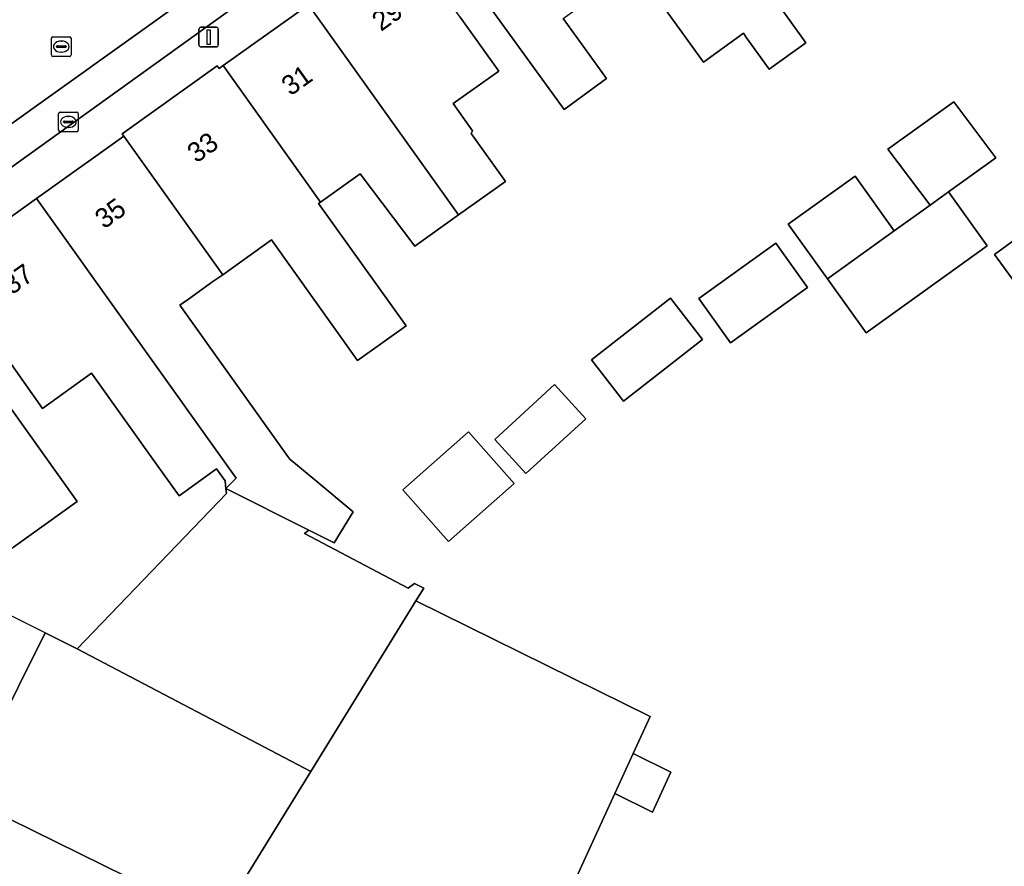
# Model space of a CAD drawing. Extents: x 161881 to 162523, y 381678 to 382381.
# Drawn here: x 162225.8 to 162276, y 381854 to 381897.2 of the extents above; entities that cross this region are included whole.
import ezdxf

# ---------------------------------------------------------------- set-up
doc = ezdxf.new("R2010")
doc.units = 0
for name, color, linetype in [('IMGEO_Erf', 7, 'Continuous'), ('IMGEO_Kolk', 7, 'Continuous'), ('IMGEO_Lichtmast', 7, 'Continuous'), ('IMGEO_Muur', 7, 'Continuous'), ('IMGEO_Pand', 7, 'Continuous'), ('IMGEO_Pand_nummerreeks', 7, 'Continuous'), ('IMGEO_Parkeervlak_open', 7, 'Continuous'), ('IMGEO_Rijbaan_lokaal_open', 7, 'Continuous'), ('IMGEO_Rioolput', 7, 'Continuous'), ('IMGEO_Voetpad_open', 7, 'Continuous')]:
    doc.layers.add(name, color=color, linetype=linetype)

msp = doc.modelspace()

# ---------------------------------------------------------------- linework, layer by layer
at = {"layer": 'IMGEO_Erf'}
for points in [[(162275.507, 381885.197), (162313.123, 381912.663)], [(162308.695, 381857.661), (162317.651, 381867.68), (162320.093, 381870.515), (162317.508, 381873.557), (162311.416, 381880.988), (162315.774, 381884.648), (162315.994, 381884.379), (162316.488, 381884.836), (162316.601, 381884.938), (162316.382, 381885.179), (162318.764, 381887.154), (162318.965, 381886.995), (162319.543, 381887.466), (162319.343, 381887.695), (162320.508, 381888.575), (162315.645, 381894.334), (162318.477, 381896.725), (162315.068, 381901.394), (162281.55, 381876.921), (162275.507, 381885.197)], [(162264.379, 381898.084), (162265.634, 381896.34), (162265.889, 381895.985), (162264.029, 381894.644), (162262.875, 381896.245), (162262.711, 381896.473), (162260.672, 381895.006), (162257.18, 381899.854)], [(162253.538, 381897.228), (162255.74, 381894.172), (162253.587, 381892.585), (162249.531, 381898.176)], [(162248.275, 381897.298), (162250.244, 381894.539), (162247.927, 381892.886), (162248.913, 381891.505), (162248.847, 381891.36), (162250.584, 381888.924), (162248.192, 381887.217), (162245.971, 381885.632), (162243.185, 381889.307), (162241.169, 381887.869), (162241.073, 381887.8), (162245.526, 381881.56), (162243.055, 381879.797), (162238.667, 381885.947), (162236.184, 381884.174), (162235.689, 381883.821), (162234.438, 381882.929), (162234.169, 381882.738), (162233.998, 381882.616), (162239.502, 381874.904), (162239.606, 381874.779), (162240.874, 381873.726), (162242.835, 381872.099), (162241.869, 381870.506), (162240.58, 381871.155), (162240.359, 381870.997), (162245.637, 381868.209), (162245.964, 381868.442), (162246.426, 381868.21), (162246.025, 381867.559), (162257.963, 381861.674), (162257.873, 381861.479), (162257.093, 381859.777), (162259.021, 381858.827), (162258.089, 381856.793), (162256.161, 381857.743), (162252.342, 381849.408)], [(162220.983, 381883.545), (162228.778, 381872.621), (162225.523, 381870.299)], [(162224.418, 381860.495), (162227.131, 381865.927), (162228.776, 381865.106), (162236.37, 381873.024), (162236.344, 381873.289), (162236.307, 381873.673), (162235.876, 381874.277), (162233.959, 381872.909), (162232.792, 381874.544), (162229.505, 381879.151), (162227.003, 381877.365), (162224.754, 381880.517)]]:
    msp.add_lwpolyline(points, dxfattribs=at)
for points in [[(162268.967, 381881.211), (162266.993, 381883.962), (162264.999, 381886.74), (162268.406, 381889.186), (162270.4, 381886.408), (162272.22, 381887.715), (162270.067, 381890.562), (162273.428, 381892.975), (162275.581, 381890.128), (162273.16, 381888.39), (162275.134, 381885.639)], [(162262.055, 381880.707), (162260.435, 381882.963), (162264.362, 381885.782), (162265.981, 381883.526)], [(162258.99, 381882.972), (162260.627, 381880.876), (162256.61, 381877.739), (162254.973, 381879.836)], [(162250.041, 381875.78), (162253.095, 381878.579), (162254.69, 381876.839), (162251.636, 381874.04)], [(162247.681, 381870.576), (162245.353, 381873.207), (162248.707, 381876.176), (162251.035, 381873.545)]]:
    msp.add_lwpolyline(points, close=True, dxfattribs=at)
at = {"layer": 'IMGEO_Kolk'}
for p, q in [((162227.897, 381892.457), (162228.749, 381892.457)), ((162227.822, 381891.531), (162227.822, 381892.383)), ((162228.081, 381891.951), (162228.081, 381891.963)), ((162228.124, 381892), (162228.522, 381892)), ((162228.31, 381892.237), (162228.335, 381892.237)), ((162228.565, 381891.963), (162228.565, 381891.951)), ((162228.823, 381892.383), (162228.823, 381891.531)), ((162228.749, 381891.457), (162227.897, 381891.457)), ((162228.519, 381891.914), (162228.121, 381891.914)), ((162228.333, 381891.677), (162228.308, 381891.677))]:
    msp.add_line(p, q, dxfattribs=at)
for points in [[(162227.897, 381892.457), (162228.749, 381892.457)], [(162227.822, 381891.531), (162227.822, 381892.383)], [(162228.823, 381892.383), (162228.823, 381891.531)], [(162228.749, 381891.457), (162227.897, 381891.457)]]:
    msp.add_lwpolyline(points, dxfattribs=at)
for centre, radius, start, end in [((162227.899, 381892.381), 0.0765, 91.552, 178.448), ((162227.899, 381892.381), 0.0765, 91.552, 178.448), ((162228.747, 381892.381), 0.0765, 1.552, 88.448), ((162228.747, 381892.381), 0.0765, 1.552, 88.448), ((162228.121, 381891.96), 0.0403, 85.8775, 175.7526), ((162228.118, 381891.95), 0.0366, 178.938, 274.7102), ((162228.522, 381891.957), 0.043, 264.8664, 352.4533), ((162228.526, 381891.962), 0.0386, 1.7309, 96.639), ((162227.899, 381891.533), 0.0765, 181.552, 268.448), ((162227.899, 381891.533), 0.0765, 181.552, 268.448), ((162228.747, 381891.533), 0.0765, 271.552, 358.448), ((162228.747, 381891.533), 0.0765, 271.552, 358.448)]:
    msp.add_arc(centre, radius, start, end, dxfattribs=at)
for centre, major_axis, ratio, start_param, end_param in [((162228.309, 381891.957), (-0.387, 0.002), 0.722429, 4.712389, 7.853982), ((162228.334, 381891.957), (-0.39, 0.002), 0.717154, 1.570796, 4.712389)]:
    msp.add_ellipse(centre, major_axis=major_axis, ratio=ratio, start_param=start_param, end_param=end_param, dxfattribs=at)
at = {"layer": 'IMGEO_Lichtmast'}
for p, q in [((162234.971, 381895.879), (162234.971, 381896.679)), ((162234.971, 381896.679), (162234.971, 381895.879)), ((162235.071, 381896.779), (162235.861, 381896.779)), ((162235.861, 381896.779), (162235.071, 381896.779)), ((162235.961, 381896.679), (162235.961, 381895.879)), ((162235.961, 381895.879), (162235.961, 381896.679)), ((162235.861, 381895.779), (162235.071, 381895.779)), ((162235.071, 381895.779), (162235.861, 381895.779))]:
    msp.add_line(p, q, dxfattribs=at)
msp.add_lwpolyline([(162235.391, 381896.654), (162235.541, 381896.654), (162235.541, 381895.904), (162235.391, 381895.904), (162235.391, 381896.654)], dxfattribs=at)
for centre, start, end in [((162235.071, 381896.679), 90, 180), ((162235.071, 381896.679), 90, 180), ((162235.861, 381896.679), 0, 90), ((162235.861, 381896.679), 360, 90), ((162235.071, 381895.879), 180, 270), ((162235.071, 381895.879), 180, 270), ((162235.861, 381895.879), 270, 0), ((162235.861, 381895.879), 270, 0)]:
    msp.add_arc(centre, 0.1, start, end, dxfattribs=at)
at = {"layer": 'IMGEO_Muur'}
msp.add_lwpolyline([(162227.131, 381865.927), (162221.091, 381868.944)], dxfattribs=at)
at = {"layer": 'IMGEO_Pand'}
for points in [[(162315.068, 381901.394), (162318.477, 381896.725), (162315.645, 381894.334), (162320.508, 381888.575), (162331.126, 381897.517), (162324.457, 381905.392), (162322.762, 381907.393), (162318.985, 381904.635), (162313.123, 381912.663), (162275.507, 381885.197), (162281.55, 381876.921)], [(162256.346, 381909.25), (162252.439, 381906.434), (162255.362, 381902.378), (162257.18, 381899.854), (162260.672, 381895.006), (162262.711, 381896.473), (162262.875, 381896.245), (162264.029, 381894.644), (162265.889, 381895.985), (162265.634, 381896.34), (162264.379, 381898.084), (162263.328, 381899.545)], [(162251.586, 381905.819), (162246.608, 381902.233), (162249.531, 381898.176), (162253.587, 381892.585), (162255.74, 381894.172), (162253.538, 381897.228), (162256.328, 381899.238), (162254.509, 381901.762)], [(162248.275, 381897.298), (162245.371, 381901.367), (162240.549, 381897.926), (162248.192, 381887.217), (162250.584, 381888.924), (162248.847, 381891.36), (162248.913, 381891.505), (162247.927, 381892.886), (162250.244, 381894.539)], [(162248.192, 381887.217), (162240.549, 381897.926), (162236.204, 381894.826), (162241.169, 381887.869), (162243.185, 381889.307), (162245.971, 381885.632)], [(162241.073, 381887.8), (162241.169, 381887.869), (162236.204, 381894.826), (162235.998, 381894.679), (162235.903, 381894.812), (162231.059, 381891.355), (162231.152, 381891.225), (162236.184, 381884.174), (162238.667, 381885.947), (162243.055, 381879.797), (162245.526, 381881.56)], [(162272.22, 381887.715), (162273.16, 381888.39), (162275.581, 381890.128), (162273.428, 381892.975), (162270.067, 381890.562)], [(162231.152, 381891.225), (162226.702, 381888.049), (162236.869, 381873.804), (162236.344, 381873.289), (162240.58, 381871.155), (162241.869, 381870.506), (162242.835, 381872.099), (162240.874, 381873.726), (162239.606, 381874.779), (162239.502, 381874.904), (162233.998, 381882.616), (162234.169, 381882.738), (162234.438, 381882.929), (162235.689, 381883.821), (162236.184, 381884.174)], [(162264.999, 381886.74), (162266.993, 381883.962), (162270.4, 381886.408), (162268.406, 381889.186)], [(162226.702, 381888.049), (162221.85, 381884.587), (162224.754, 381880.517), (162227.003, 381877.365), (162229.505, 381879.151), (162232.792, 381874.544), (162233.959, 381872.909), (162235.876, 381874.277), (162236.307, 381873.673), (162236.344, 381873.289), (162236.869, 381873.804)], [(162275.134, 381885.639), (162273.16, 381888.39), (162272.22, 381887.715), (162270.4, 381886.408), (162266.993, 381883.962), (162268.967, 381881.211)], [(162260.435, 381882.963), (162262.055, 381880.707), (162265.981, 381883.526), (162264.362, 381885.782)], [(162220.983, 381883.545), (162219.932, 381882.795), (162219.757, 381883.039), (162214.81, 381879.508), (162214.928, 381879.343), (162215.074, 381879.138), (162214.585, 381878.789), (162215.841, 381877.029), (162216.329, 381877.377), (162219.836, 381872.464), (162220.024, 381872.598), (162224.95, 381870.164), (162225.045, 381870.118), (162225.177, 381870.052), (162225.523, 381870.299), (162228.778, 381872.621)], [(162258.99, 381882.972), (162254.973, 381879.836), (162256.61, 381877.739), (162260.627, 381880.876)], [(162250.041, 381875.78), (162251.636, 381874.04), (162254.69, 381876.839), (162253.095, 381878.579)], [(162248.707, 381876.176), (162245.353, 381873.207), (162247.681, 381870.576), (162251.035, 381873.545)], [(162240.359, 381870.997), (162240.58, 381871.155), (162236.344, 381873.289), (162236.37, 381873.024), (162228.776, 381865.106), (162240.666, 381858.867), (162246.025, 381867.559), (162246.426, 381868.21), (162245.964, 381868.442), (162245.637, 381868.209)], [(162222.972, 381857.598), (162220.321, 381858.911), (162211.275, 381863.392), (162201.278, 381868.442), (162200.189, 381868.993), (162191.173, 381862.471), (162202.159, 381857.074), (162201.802, 381856.284), (162194.508, 381840.175), (162203.692, 381835.979), (162211.21, 381852.547), (162219.706, 381848.467), (162222.963, 381846.903), (162225.821, 381845.53), (162230.931, 381843.076), (162232.406, 381845.468), (162235.949, 381851.214)], [(162252.342, 381849.408), (162256.161, 381857.743), (162257.093, 381859.777), (162257.873, 381861.479), (162257.963, 381861.674), (162246.025, 381867.559), (162240.666, 381858.867), (162235.949, 381851.214), (162232.406, 381845.468), (162238.196, 381842.822), (162238.73, 381843.992), (162242.567, 381842.238), (162241.739, 381840.426), (162234.507, 381824.125), (162235.421, 381823.701), (162236.604, 381820.938), (162238.114, 381820.275), (162238.061, 381820.148), (162238.59, 381819.884), (162238.733, 381819.87), (162242.059, 381827.149), (162244.506, 381832.34), (162249.124, 381842.446)], [(162228.776, 381865.106), (162227.131, 381865.927), (162224.418, 381860.495), (162222.972, 381857.598), (162235.949, 381851.214), (162240.666, 381858.867)], [(162257.093, 381859.777), (162256.161, 381857.743), (162258.089, 381856.793), (162259.021, 381858.827)]]:
    msp.add_lwpolyline(points, close=True, dxfattribs=at)
at = {"layer": 'IMGEO_Parkeervlak_open'}
msp.add_lwpolyline([(162273.463, 381926.395), (162269.991, 381923.887), (162260.256, 381916.887), (162257.825, 381915.139), (162253.349, 381911.92), (162238.365, 381901.138), (162234.555, 381898.412), (162224.359, 381891.116), (162225.354, 381889.595), (162274.088, 381924.659), (162273.358, 381925.677)], dxfattribs=at)
at = {"layer": 'IMGEO_Rijbaan_lokaal_open'}
msp.add_lwpolyline([(162221.475, 381894.082), (162223.84, 381890.752), (162224.359, 381891.116), (162234.555, 381898.412)], dxfattribs=at)
at = {"layer": 'IMGEO_Rioolput'}
for p, q in [((162227.459, 381895.366), (162227.459, 381896.218)), ((162227.534, 381896.292), (162228.386, 381896.292)), ((162227.947, 381896.072), (162227.972, 381896.072)), ((162228.46, 381896.218), (162228.46, 381895.366)), ((162227.718, 381895.786), (162227.718, 381895.798)), ((162228.156, 381895.749), (162227.758, 381895.749)), ((162227.761, 381895.835), (162228.159, 381895.835)), ((162227.97, 381895.512), (162227.945, 381895.512)), ((162228.202, 381895.798), (162228.202, 381895.786)), ((162228.386, 381895.292), (162227.534, 381895.292))]:
    msp.add_line(p, q, dxfattribs=at)
for points in [[(162227.459, 381895.366), (162227.459, 381896.218)], [(162227.534, 381896.292), (162228.386, 381896.292)], [(162228.46, 381896.218), (162228.46, 381895.366)], [(162228.386, 381895.292), (162227.534, 381895.292)]]:
    msp.add_lwpolyline(points, dxfattribs=at)
for centre, radius, start, end in [((162227.536, 381896.216), 0.0765, 91.552, 178.448), ((162227.536, 381896.216), 0.0765, 91.552, 178.448), ((162228.384, 381896.216), 0.0765, 1.552, 88.448), ((162228.384, 381896.216), 0.0765, 1.552, 88.448), ((162227.758, 381895.795), 0.0403, 85.8775, 175.7526), ((162227.755, 381895.785), 0.0366, 178.938, 274.7102), ((162228.159, 381895.792), 0.043, 264.8664, 352.4533), ((162228.163, 381895.797), 0.0386, 1.7309, 96.639), ((162227.536, 381895.368), 0.0765, 181.552, 268.448), ((162227.536, 381895.368), 0.0765, 181.552, 268.448), ((162228.384, 381895.368), 0.0765, 271.552, 358.448), ((162228.384, 381895.368), 0.0765, 271.552, 358.448)]:
    msp.add_arc(centre, radius, start, end, dxfattribs=at)
for centre, major_axis, ratio, start_param, end_param in [((162227.946, 381895.792), (-0.387, 0.002), 0.722429, 4.712389, 7.853982), ((162227.971, 381895.792), (-0.39, 0.002), 0.717154, 1.570796, 4.712389)]:
    msp.add_ellipse(centre, major_axis=major_axis, ratio=ratio, start_param=start_param, end_param=end_param, dxfattribs=at)
at = {"layer": 'IMGEO_Voetpad_open'}
for points in [[(162273.358, 381925.677), (162274.088, 381924.659), (162225.354, 381889.595), (162224.004, 381888.624), (162214.822, 381882.018), (162214.15, 381883.202)], [(162221.85, 381884.587), (162226.702, 381888.049), (162231.152, 381891.225), (162231.059, 381891.355), (162235.903, 381894.812), (162235.998, 381894.679), (162236.204, 381894.826), (162240.549, 381897.926)]]:
    msp.add_lwpolyline(points, dxfattribs=at)

# ---------------------------------------------------------------- texts
at = {"layer": 'IMGEO_Pand_nummerreeks'}
for s, rotation, p in [('29', 35.5062, (162244.251, 381896.538)), ('31', 35.5043, (162239.639, 381893.248)), ('33', 35.5062, (162234.843, 381889.826)), ('35', 35.5062, (162230.139, 381886.47)), ('37', 35.5062, (162225.434, 381883.114))]:
    msp.add_text(s, height=1, rotation=rotation, dxfattribs=at).set_placement(p)

doc.saveas('drawing.dxf')
